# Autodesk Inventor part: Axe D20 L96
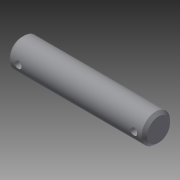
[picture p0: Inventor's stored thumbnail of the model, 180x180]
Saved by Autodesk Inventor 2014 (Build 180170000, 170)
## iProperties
Created: 2015-09
Part Number: Axe D20 L96
Material: Générique
Document SubType Name: Modeling
Designer: OL
Density: 1 g/cm^3
Appearance: Par défaut
Author: OL
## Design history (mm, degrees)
sketch "Esquisse1"
  geometry: C1 r 10 at (0, 0); 1 further point
  constraints: 1 centre point, 1 coincident
  dimensions: "d0" = 20 diameter of C1
extrude "Extrusion1" new body sketch "Esquisse1" distance "d2" = 96; taper "d3" = 0 deg
chamfer "Chanfrein1" distance "d4" = 2; stored, may be unused: second distance "d5" = 2, angle "d6" = 45 deg
sketch "Esquisse2"
  geometry: C1 r 2.5 at (-88.5, 0); C2 r 2.5 at (-7.5, 0); 1 further point
  constraints: 2 centre point
  dimensions: "d7" = 5 diameter of C1; "d9" = 5 diameter of C2; "d10" = 7.5 distance of point (0, 0) C2.centre; "d11" = 88.5 distance of point (0, 0) C1.centre
extrude "Extrusion2" cut sketch "Esquisse2" stored distance "d13" = 100; taper "d14" = 0 deg
node "Solide1"
